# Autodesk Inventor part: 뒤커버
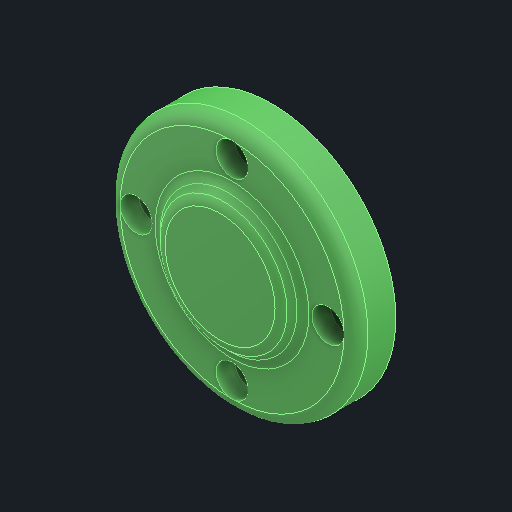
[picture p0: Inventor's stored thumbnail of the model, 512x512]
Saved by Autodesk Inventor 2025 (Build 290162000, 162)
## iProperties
Created: 2025-08
Part Number: 뒤커버
Material: 알루미늄 6061
Document SubType Name: Modeling
Designer: infra012
Density: 2.71 g/cm^3
Appearance: 기본값
Author: jhkim
Sending System: Autodesk Inventor 2026
Preprocessor: ST-DEVELOPER v20.1
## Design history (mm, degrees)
sketch "스케치1"
  geometry: 1 further point
  constraints: 1 other
feature "솔리드1"
node "솔리드2"
